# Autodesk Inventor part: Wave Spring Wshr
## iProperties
Shininess: 64.0
Length Units: 11272
Angle Units: 11279
Time Units: 11290
Mass Units: 11286
Length Display Precision: 3
Angle Display Precision: 2
Manager: Cory McConnell
Company: Mechanix Design Solutions
Created: 2002-04
Part Number: Wave Spring Wshr
Material: Steel, High Strength Low Alloy
Description: ASS'C SPRING WAVE SPRING WSHR
Document SubType Name: Modeling
Designer: CM
Density: 10.49
Volumn: 2.304646865681294
Area: 8.437628188859923
PropertySet Name: Model Information
Control State: 0
Master: False
Checked Out: False
Author: CM
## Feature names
1. Sweep1
2. Extrusion2
